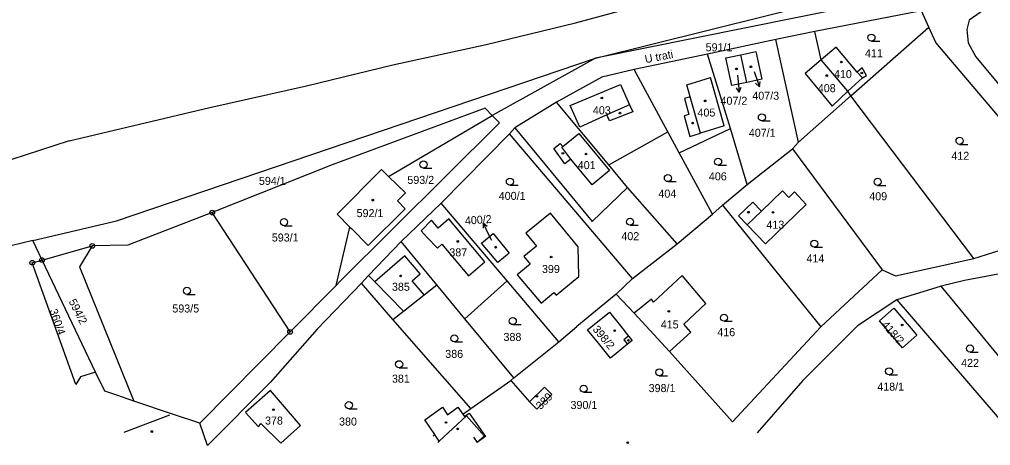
# Model space of a CAD drawing. Extents: x -776701 to -776081, y -974398 to -973771.
# Drawn here: x -776586.6 to -776380.3, y -974398.1 to -974307.7 of the extents above; entities that cross this region are included whole.
import ezdxf

# ---------------------------------------------------------------- set-up
doc = ezdxf.new("R2010")
doc.units = 0
for name, color, linetype in [('Hranice parcel', 7, 'Continuous'), ('Parcelní čísla', 7, 'Continuous'), ('Pop  PČ popisy', 7, 'Continuous'), ('Poz předměty', 7, 'Continuous'), ('Vnitřní kresba', 7, 'Continuous'), ('Značky bodu BP', 7, 'Continuous'), ('Značky budov', 7, 'Continuous'), ('Značky kultur', 7, 'Continuous')]:
    doc.layers.add(name, color=color, linetype=linetype)

msp = doc.modelspace()

# ---------------------------------------------------------------- linework, layer by layer
at = {"layer": 'Hranice parcel'}
for p, q in [((-776380.5, -974299.02), (-776464.24, -974315.93)), ((-776395.04, -974305.86), (-776417.64, -974310.29)), ((-776393.45, -974309.32), (-776395.04, -974305.86)), ((-776417.64, -974310.29), (-776425.93, -974311.95)), ((-776416.33, -974316.29), (-776417.64, -974310.29)), ((-776409.99, -974323.88), (-776393.45, -974309.32)), ((-776425.93, -974311.95), (-776440.43, -974315.06)), ((-776421.16, -974333.7), (-776425.93, -974311.95)), ((-776440.43, -974315.06), (-776456.01, -974318.31)), ((-776435.6, -974330.8), (-776440.43, -974315.06)), ((-776432.11, -974321.05), (-776433.37, -974315.18)), ((-776464.24, -974315.93), (-776486.21, -974328.09)), ((-776410.68, -974322.95), (-776416.33, -974316.29)), ((-776448.86, -974331.51), (-776456.01, -974318.31)), ((-776409.99, -974323.88), (-776410.68, -974322.95)), ((-776472.53, -974325.25), (-776481.39, -974330.69)), ((-776461.43, -974338.52), (-776472.53, -974325.25)), ((-776421.16, -974333.7), (-776409.99, -974323.88)), ((-776383.87, -974358.38), (-776409.99, -974323.88)), ((-776508.16, -974341), (-776486.21, -974328.09)), ((-776481.39, -974330.69), (-776482.51, -974331.97)), ((-776461.43, -974338.52), (-776448.86, -974331.51)), ((-776446.44, -974335.99), (-776448.86, -974331.51)), ((-776446.44, -974335.99), (-776435.6, -974330.8)), ((-776432.03, -974342.7), (-776435.6, -974330.8)), ((-776482.51, -974331.97), (-776496.98, -974346.68)), ((-776456.36, -974362.65), (-776482.51, -974331.97)), ((-776422.4, -974335.15), (-776421.16, -974333.7)), ((-776439.4, -974349), (-776446.44, -974335.99)), ((-776432.03, -974342.7), (-776422.4, -974335.15)), ((-776422.4, -974335.15), (-776403.36, -974360.84)), ((-776457.41, -974343.32), (-776461.43, -974338.52)), ((-776446.9, -974355.3), (-776457.41, -974343.32)), ((-776437.28, -974347.12), (-776432.03, -974342.7)), ((-776496.98, -974346.68), (-776505.5, -974354.8)), ((-776483.01, -974363.16), (-776496.98, -974346.68)), ((-776439.4, -974349), (-776437.28, -974347.12)), ((-776437.28, -974347.12), (-776416.39, -974372.9)), ((-776529.08, -974373.98), (-776545.61, -974348.67)), ((-776446.9, -974355.3), (-776439.4, -974349)), ((-776519.33, -974364.13), (-776516.39, -974351.73)), ((-776583.73, -974354.62), (-776590.8, -974356.28)), ((-776581.76, -974358.74), (-776583.73, -974354.62)), ((-776581.76, -974358.74), (-776571.09, -974355.74)), ((-776497.92, -974363.96), (-776505.5, -974354.8)), ((-776456.36, -974362.65), (-776446.9, -974355.3)), ((-776570.41, -974382.5), (-776581.76, -974358.74)), ((-776459.84, -974365.96), (-776456.36, -974362.65)), ((-776416.39, -974372.9), (-776403.36, -974360.84)), ((-776519.33, -974364.13), (-776529.08, -974373.98)), ((-776513.93, -974363.63), (-776523.33, -974373.43)), ((-776507.27, -974371.32), (-776513.93, -974363.63)), ((-776491.96, -974371.17), (-776497.92, -974363.96)), ((-776491.96, -974371.17), (-776483.01, -974363.16)), ((-776472, -974376.1), (-776483.01, -974363.16)), ((-776390.84, -974364.25), (-776400.26, -974367.17)), ((-776371.4, -974387.94), (-776390.84, -974364.25)), ((-776459.84, -974365.96), (-776468.2, -974372.8)), ((-776456.02, -974370.01), (-776459.84, -974365.96)), ((-776400.26, -974367.17), (-776376.3, -974394.94)), ((-776448.55, -974378.15), (-776456.02, -974370.01)), ((-776490.7, -974390.2), (-776507.27, -974371.32)), ((-776481.59, -974383.7), (-776491.96, -974371.17)), ((-776472, -974376.1), (-776468.2, -974372.8)), ((-776435.14, -974393.04), (-776416.39, -974372.9)), ((-776529.08, -974373.98), (-776548.25, -974393.33)), ((-776523.33, -974373.43), (-776533.29, -974384.74)), ((-776481.59, -974383.7), (-776472, -974376.1)), ((-776435.14, -974393.04), (-776448.55, -974378.15)), ((-776568.46, -974386.58), (-776570.41, -974382.5)), ((-776533.29, -974384.74), (-776546.65, -974398.08)), ((-776490.7, -974390.2), (-776482.25, -974384.27)), ((-776482.25, -974384.27), (-776481.59, -974383.7)), ((-776482.25, -974384.27), (-776478.25, -974388.8)), ((-776420.24, -974384.28), (-776429.92, -974395.38)), ((-776554.07, -974391.39), (-776562.26, -974388.65)), ((-776478.25, -974388.8), (-776476.69, -974390.38)), ((-776548.25, -974393.33), (-776554.07, -974391.39)), ((-776492.4, -974391.43), (-776490.7, -974390.2)), ((-776546.65, -974398.08), (-776548.25, -974393.33)), ((-776497.7, -974397.4), (-776497.41, -974397.14))]:
    msp.add_line(p, q, dxfattribs=at)
for points in [[(-776464.24, -974315.93), (-776403.84, -974300.87), (-776380.5, -974299.02)], [(-776381.33, -974304.06), (-776380.93, -974305.13), (-776384.89, -974307.87), (-776385.42, -974309.83), (-776385.09, -974312.64), (-776383.44, -974315.62), (-776375.79, -974324.92)], [(-776383.87, -974358.38), (-776378.5, -974356.68), (-776375.04, -974354.64), (-776372.83, -974352.03), (-776370.62, -974348.5), (-776369.27, -974344.71), (-776368.91, -974340.64), (-776370.74, -974336.88), (-776373.7, -974334.1), (-776391.97, -974312.58), (-776393.45, -974309.32)], [(-776432.11, -974321.05), (-776435.28, -974321.73), (-776436.54, -974315.86), (-776433.37, -974315.18)], [(-776433.37, -974315.18), (-776430.2, -974314.5), (-776428.94, -974320.37), (-776432.11, -974321.05)], [(-776410.68, -974322.95), (-776407.51, -974320.1), (-776406.7, -974319.57), (-776407.6, -974318), (-776408.7, -974318.9), (-776413.15, -974313.59), (-776416.33, -974316.29)], [(-776583.73, -974354.62), (-776579.46, -974353.57), (-776565.96, -974350.44), (-776464.24, -974315.93)], [(-776456.01, -974318.31), (-776462.89, -974319.92), (-776472.53, -974325.25)], [(-776486.21, -974328.09), (-776487.7, -974326.5), (-776520.18, -974338.56), (-776545.61, -974348.67)], [(-776486.21, -974328.09), (-776484.6, -974329.63), (-776518.53, -974363.32), (-776519.33, -974364.13)], [(-776481.39, -974330.69), (-776464.95, -974350.55), (-776457.41, -974343.32)], [(-776516.39, -974351.73), (-776519.07, -974348.99), (-776509.68, -974339.52), (-776508.16, -974341)], [(-776516.39, -974351.73), (-776516, -974352.13), (-776512.54, -974355.65), (-776504.63, -974347.89), (-776506.28, -974346.21), (-776504.55, -974344.51), (-776508.16, -974341)], [(-776424.52, -974344.09), (-776428.99, -974348.38), (-776430.84, -974346.45), (-776433.86, -974349.34), (-776432.01, -974351.27), (-776428.17, -974355.27), (-776419.51, -974346.96), (-776421.96, -974344.28), (-776423.17, -974345.49), (-776424.52, -974344.09)], [(-776545.61, -974348.67), (-776563.54, -974355.57), (-776571.09, -974355.74)], [(-776467.92, -974355.94), (-776473.77, -974348.8), (-776479.02, -974353.01), (-776476.78, -974355.79), (-776479.46, -974357.95), (-776478.11, -974359.58), (-776480.84, -974361.85), (-776475.8, -974367.87), (-776473.08, -974365.63), (-776472.6, -974366.21), (-776467.76, -974362.24), (-776467.92, -974355.94)], [(-776485.97, -974353.11), (-776482.59, -974357.25), (-776485, -974359.23), (-776488.42, -974355.15), (-776485.97, -974353.11)], [(-776571.09, -974355.74), (-776573.78, -974360.2), (-776562.26, -974388.65)], [(-776505.5, -974354.8), (-776512.41, -974362.03), (-776513.93, -974363.63)], [(-776403.36, -974360.84), (-776400.53, -974362.08), (-776383.87, -974358.38)], [(-776574.59, -974385.14), (-776583.83, -974359.32), (-776581.76, -974358.74)], [(-776448.55, -974378.15), (-776444, -974374.01), (-776445.5, -974372.3), (-776440.82, -974367.93), (-776445.8, -974362), (-776451.89, -974367.65), (-776452.37, -974367.05), (-776456.02, -974370.01)], [(-776375.3, -974361.1), (-776385.85, -974363.08), (-776390.84, -974364.25)], [(-776507.27, -974371.32), (-776505.03, -974369.55), (-776500.64, -974366.1), (-776497.92, -974363.96)], [(-776400.26, -974367.17), (-776408.58, -974372.68), (-776420.24, -974384.28)], [(-776403.96, -974371.64), (-776400.86, -974368.95), (-776395.98, -974374.69), (-776399.08, -974377.35), (-776403.96, -974371.64)], [(-776457.44, -974376.6), (-776461.08, -974379.55), (-776463.6, -974376.39), (-776465.93, -974373.51), (-776461.24, -974369.78), (-776458.95, -974372.68), (-776457.22, -974374.85), (-776456.46, -974375.81), (-776457.44, -974376.6)], [(-776570.41, -974382.5), (-776573.59, -974383.51), (-776574.59, -974385.14)], [(-776562.26, -974388.65), (-776565.89, -974387.36), (-776568.46, -974386.58)], [(-776538.53, -974391.05), (-776535.8, -974394.1), (-776535.3, -974393.4), (-776531.08, -974397.59), (-776526.9, -974393.8), (-776533.28, -974386.42), (-776538.53, -974391.05)], [(-776476.69, -974390.38), (-776473.53, -974387.26), (-776475.09, -974385.68), (-776478.25, -974388.8)], [(-776497.41, -974397.14), (-776498.03, -974396.29), (-776498.38, -974395.77), (-776500.51, -974392.63), (-776496.75, -974389.97), (-776495.65, -974391.53), (-776493.44, -974389.97), (-776492.4, -974391.43)], [(-776492.4, -974391.43), (-776492.07, -974391.9), (-776491.09, -974391.2), (-776487.59, -974396.15), (-776487.72, -974396.24), (-776489.36, -974397.41)]]:
    msp.add_lwpolyline(points, dxfattribs=at)
at = {"layer": 'Pop  PČ popisy'}
for p, q in [((-776434.09, -974319.51), (-776434.02, -974320.16)), ((-776430.55, -974318.78), (-776430.42, -974319.16)), ((-776430.42, -974319.16), (-776429.44, -974322)), ((-776434.02, -974320.16), (-776433.71, -974323.15)), ((-776429.44, -974322), (-776430.24, -974321.21)), ((-776429.44, -974322), (-776429.3, -974320.89)), ((-776433.71, -974323.15), (-776434.31, -974322.2)), ((-776433.71, -974323.15), (-776433.31, -974322.1)), ((-776488.11, -974350.84), (-776488.12, -974351.96)), ((-776486.79, -974353.54), (-776488.11, -974350.84)), ((-776488.11, -974350.84), (-776487.22, -974351.52)), ((-776486.27, -974354.61), (-776486.79, -974353.54))]:
    msp.add_line(p, q, dxfattribs=at)
at = {"layer": 'Poz předměty'}
for p, q in [((-776468.46, -974308.41), (-776449.01, -974303.15)), ((-776487.45, -974313.02), (-776468.46, -974308.41)), ((-776507.25, -974317.36), (-776487.45, -974313.02)), ((-776525.63, -974321.8), (-776507.25, -974317.36)), ((-776546.14, -974326.36), (-776525.63, -974321.8)), ((-776576.01, -974333.45), (-776546.14, -974326.36)), ((-776576.01, -974333.45), (-776604.66, -974342.76))]:
    msp.add_line(p, q, dxfattribs=at)
at = {"layer": 'Vnitřní kresba'}
for p, q in [((-776416.33, -974316.29), (-776419.74, -974319.14)), ((-776419.74, -974319.14), (-776414, -974326.1)), ((-776408.7, -974318.9), (-776407.51, -974320.1)), ((-776469.6, -974325.97), (-776458.94, -974321.47)), ((-776458.94, -974321.47), (-776457.02, -974325.78)), ((-776444.81, -974321.56), (-776439.84, -974320.04)), ((-776444.1, -974324.12), (-776444.81, -974321.56)), ((-776436.92, -974330.26), (-776439.84, -974320.04)), ((-776414, -974326.1), (-776410.68, -974322.95)), ((-776441.95, -974331.82), (-776444.1, -974324.12)), ((-776467.59, -974330.53), (-776469.6, -974325.97)), ((-776457.02, -974325.78), (-776461.81, -974327.95)), ((-776456.33, -974327.3), (-776461.27, -974329.23)), ((-776457.02, -974325.78), (-776456.33, -974327.3)), ((-776461.81, -974327.95), (-776467.59, -974330.53)), ((-776461.27, -974329.23), (-776461.81, -974327.95)), ((-776471.18, -974334.68), (-776467.8, -974331.86)), ((-776467.8, -974331.86), (-776461.26, -974339.72)), ((-776436.92, -974330.26), (-776441.95, -974331.82)), ((-776473.06, -974335.11), (-776471.74, -974334)), ((-776470.72, -974338.35), (-776473.06, -974335.11)), ((-776471.74, -974334), (-776471.18, -974334.68)), ((-776471.4, -974334.8), (-776471.18, -974334.68)), ((-776469.49, -974337.33), (-776471.4, -974334.8)), ((-776469.49, -974337.33), (-776470.72, -974338.35)), ((-776464.95, -974342.79), (-776469.49, -974337.33)), ((-776461.26, -974339.72), (-776464.95, -974342.79)), ((-776432.01, -974351.27), (-776428.99, -974348.38)), ((-776499.05, -974350.31), (-776501.23, -974352.54)), ((-776497.64, -974351.94), (-776499.05, -974350.31)), ((-776495.37, -974349.97), (-776497.64, -974351.94)), ((-776487.76, -974359.12), (-776495.37, -974349.97)), ((-776501.23, -974352.54), (-776499.99, -974353.97)), ((-776499.99, -974353.97), (-776497.79, -974356.25)), ((-776497.79, -974356.25), (-776496.86, -974355.35)), ((-776496.86, -974355.35), (-776491.21, -974362.1)), ((-776504.71, -974357.85), (-776511.13, -974363.33)), ((-776501.45, -974361.63), (-776504.71, -974357.85)), ((-776491.21, -974362.1), (-776487.76, -974359.12)), ((-776512.41, -974362.03), (-776511.13, -974363.33)), ((-776503.19, -974363.13), (-776501.45, -974361.63)), ((-776511.13, -974363.33), (-776505.03, -974369.55)), ((-776500.64, -974366.1), (-776503.19, -974363.13)), ((-776457.22, -974374.85), (-776458.21, -974375.64)), ((-776458.21, -974375.64), (-776457.44, -974376.6)), ((-776564.35, -974395.21), (-776554.61, -974391.59)), ((-776497.41, -974397.14), (-776491.6, -974391.8)), ((-776491.6, -974391.8), (-776487.8, -974396.1)), ((-776498.7, -974396), (-776498.38, -974395.77)), ((-776490.16, -974396.28), (-776489.36, -974397.41)), ((-776487.8, -974396.1), (-776489.36, -974397.41)), ((-776487.72, -974396.24), (-776487.8, -974396.1))]:
    msp.add_line(p, q, dxfattribs=at)
msp.add_lwpolyline([(-776444.1, -974324.12), (-776445.36, -974324.47), (-776444.39, -974327.9), (-776445.4, -974328.18), (-776444.18, -974332.51), (-776441.95, -974331.82)], dxfattribs=at)
at = {"layer": 'Značky bodu BP'}
for centre, radius in [((-776545.61, -974348.67), 0.5), ((-776545.61, -974348.67), 0.0303), ((-776571.09, -974355.74), 0.5), ((-776571.09, -974355.74), 0.0303), ((-776581.76, -974358.74), 0.5), ((-776581.76, -974358.74), 0.0303), ((-776583.83, -974359.32), 0.5), ((-776583.83, -974359.32), 0.0303), ((-776529.08, -974373.98), 0.5), ((-776529.08, -974373.98), 0.0303)]:
    msp.add_circle(centre, radius, dxfattribs=at)
at = {"layer": 'Značky budov'}
for centre in [(-776412.04, -974316.74), (-776434.31, -974318.19), (-776431.25, -974317.75), (-776415.13, -974319.61), (-776407.68, -974319.08), (-776462.88, -974324.35), (-776440.95, -974324.98), (-776459.02, -974327.58), (-776443.62, -974329.69), (-776471.16, -974336.1), (-776466.25, -974336.25), (-776511.52, -974346.03), (-776431.75, -974348.59), (-776426.54, -974348.62), (-776493.48, -974354.79), (-776485.45, -974356.01), (-776473.65, -974358.09), (-776505.6, -974362.09), (-776448.68, -974369.62), (-776399.1, -974372.5), (-776460.16, -974373.7), (-776457.26, -974375.75), (-776476.68, -974387.65), (-776532.62, -974390.47), (-776495.98, -974393.19), (-776558.45, -974395.11), (-776493.52, -974394.54), (-776457.4, -974397.48)]:
    msp.add_circle(centre, 0.175, dxfattribs=at)
at = {"layer": 'Značky kultur'}
for p, q in [((-776405.64, -974312.31), (-776403.89, -974312.31)), ((-776428.9, -974329.22), (-776427.15, -974329.22)), ((-776386.93, -974334.2), (-776385.18, -974334.2)), ((-776500.76, -974339.22), (-776499.01, -974339.22)), ((-776438.2, -974338.63), (-776436.45, -974338.63)), ((-776448.87, -974342.11), (-776447.12, -974342.11)), ((-776482.41, -974342.86), (-776480.66, -974342.86)), ((-776404.33, -974342.89), (-776402.58, -974342.89)), ((-776530.37, -974351.45), (-776528.62, -974351.45)), ((-776456.91, -974351.36), (-776455.16, -974351.36)), ((-776417.78, -974356.01), (-776416.03, -974356.01)), ((-776550.99, -974366.01), (-776549.24, -974366.01)), ((-776481.8, -974372.43), (-776480.05, -974372.43)), ((-776436.94, -974371.72), (-776435.19, -974371.72)), ((-776494.21, -974376.1), (-776492.46, -974376.1)), ((-776384.71, -974378.24), (-776382.96, -974378.24)), ((-776505.93, -974381.58), (-776504.18, -974381.58)), ((-776450.69, -974383.3), (-776448.94, -974383.3)), ((-776401.89, -974383.08), (-776400.14, -974383.08)), ((-776466.75, -974386.78), (-776465, -974386.78)), ((-776516.61, -974390.27), (-776514.86, -974390.27))]:
    msp.add_line(p, q, dxfattribs=at)
for centre in [(-776405.64, -974311.56), (-776428.9, -974328.47), (-776386.93, -974333.45), (-776500.76, -974338.47), (-776438.2, -974337.88), (-776482.41, -974342.11), (-776448.87, -974341.36), (-776404.33, -974342.14), (-776530.37, -974350.7), (-776456.91, -974350.61), (-776417.78, -974355.26), (-776550.99, -974365.26), (-776481.8, -974371.68), (-776436.94, -974370.97), (-776494.21, -974375.35), (-776384.71, -974377.49), (-776505.93, -974380.83), (-776450.69, -974382.55), (-776401.89, -974382.33), (-776466.75, -974386.03), (-776516.61, -974389.52)]:
    msp.add_circle(centre, 0.75, dxfattribs=at)

# ---------------------------------------------------------------- texts
at = {"layer": 'Parcelní čísla'}
for s, p in [('591/1', (-776440.85, -974314.46)), ('411', (-776407.01, -974315.71)), ('410', (-776413.6, -974320.14)), ('408', (-776417.03, -974323.13)), ('407/3', (-776430.93, -974324.73)), ('407/2', (-776437.69, -974325.8)), ('403', (-776464.79, -974327.82)), ('405', (-776442.58, -974328.3)), ('407/1', (-776431.68, -974332.59)), ('412', (-776388.67, -974337.48)), ('401', (-776468, -974339.45)), ('406', (-776440.16, -974341.83)), ('594/1', (-776535.71, -974342.79)), ('593/2', (-776504.19, -974342.59)), ('400/1', (-776484.78, -974345.98)), ('404', (-776450.88, -974345.5)), ('409', (-776406.1, -974346.05)), ('592/1', (-776514.96, -974349.63)), ('413', (-776427.94, -974352.09)), ('593/1', (-776532.97, -974354.8)), ('402', (-776458.74, -974354.52)), ('387', (-776495.27, -974357.95)), ('414', (-776419.44, -974359.24)), ('399', (-776475.6, -974361.48)), ('385', (-776507.46, -974365.25)), ('593/5', (-776554.09, -974369.86)), ('415', (-776450.37, -974373.24)), ('388', (-776483.77, -974375.89)), ('416', (-776438.38, -974374.88)), ('386', (-776496.14, -974379.49)), ('422', (-776386.59, -974381.4)), ('381', (-776507.46, -974384.74)), ('398/1', (-776452.95, -974386.74)), ('418/1', (-776404.4, -974386.44)), ('390/1', (-776469.54, -974390.32)), ('378', (-776534.41, -974393.63)), ('380', (-776518.69, -974393.84))]:
    msp.add_text(s, height=1.7, dxfattribs=at).set_placement(p)
for s, rotation, p in [('400/2', 4, (-776491.91, -974351.25)), ('594/2', 297, (-776576.16, -974367.5)), ('360/4', 289, (-776580.19, -974369.42)), ('398/2', 310, (-776464.96, -974373.49)), ('418/2', 312, (-776403.6, -974372.59)), ('389', 45, (-776475.88, -974390.58))]:
    msp.add_text(s, height=1.7, rotation=rotation, dxfattribs=at).set_placement(p)
at = {"layer": 'Pop  PČ popisy'}
msp.add_text('U trati', height=1.7, rotation=11, dxfattribs=at).set_placement((-776453.58, -974317))

doc.saveas('drawing.dxf')
